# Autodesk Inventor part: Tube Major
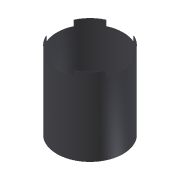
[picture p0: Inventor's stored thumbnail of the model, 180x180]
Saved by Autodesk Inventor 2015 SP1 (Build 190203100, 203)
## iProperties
Category: Mechanical Engineering Drawing and Design - CADD
Manager: Fábio Ricardo de Oliveira Souza
Company: SENAI - Serviço Nacional de Aprendizagem Industrial
Created: 2011-06
Part Number: Tube Major
Material: Steel
Description: Stainless Steel (DIN- X6CrNiTi18-10)
Document SubType Name: Modeling
Designer: Guilherme Augusto Franco de Souza
Engineer: George Geraldo de Oliveia Silva
Authority: Fábio Ricardo de Oliveira Soza
Density: 7.85 g/cm^3
Mass: 2462.28 g
Surface Area: 6294.2 cm^2
Volume: 313.667 cm^3
Appearance: Machined 02
Subject: WorldSkill 2011 - London, England
Author: Guilherme Augusto Franco de Souza
Revision Number: 00
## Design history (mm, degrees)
derived "Tube.ipt"
body "Solid2"
feature "Solid2::Tube.ipt"
tag "TaggingFeature1"
other parameters: "d6" = 25, "d7" = 125, "d9" = 0, "d11" = 90 deg, "Diam_ext" = 298, "d4" = 0, "d5" = 1
